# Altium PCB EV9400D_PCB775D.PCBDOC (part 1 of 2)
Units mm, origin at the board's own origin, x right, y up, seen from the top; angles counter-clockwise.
Board outline 83 x 87.15 mm, 4 copper layers (Top, L2C, L3C, Bottom), stack 1.546 mm thick; 203 components, 103 nets, 489 pads, 604 vias.
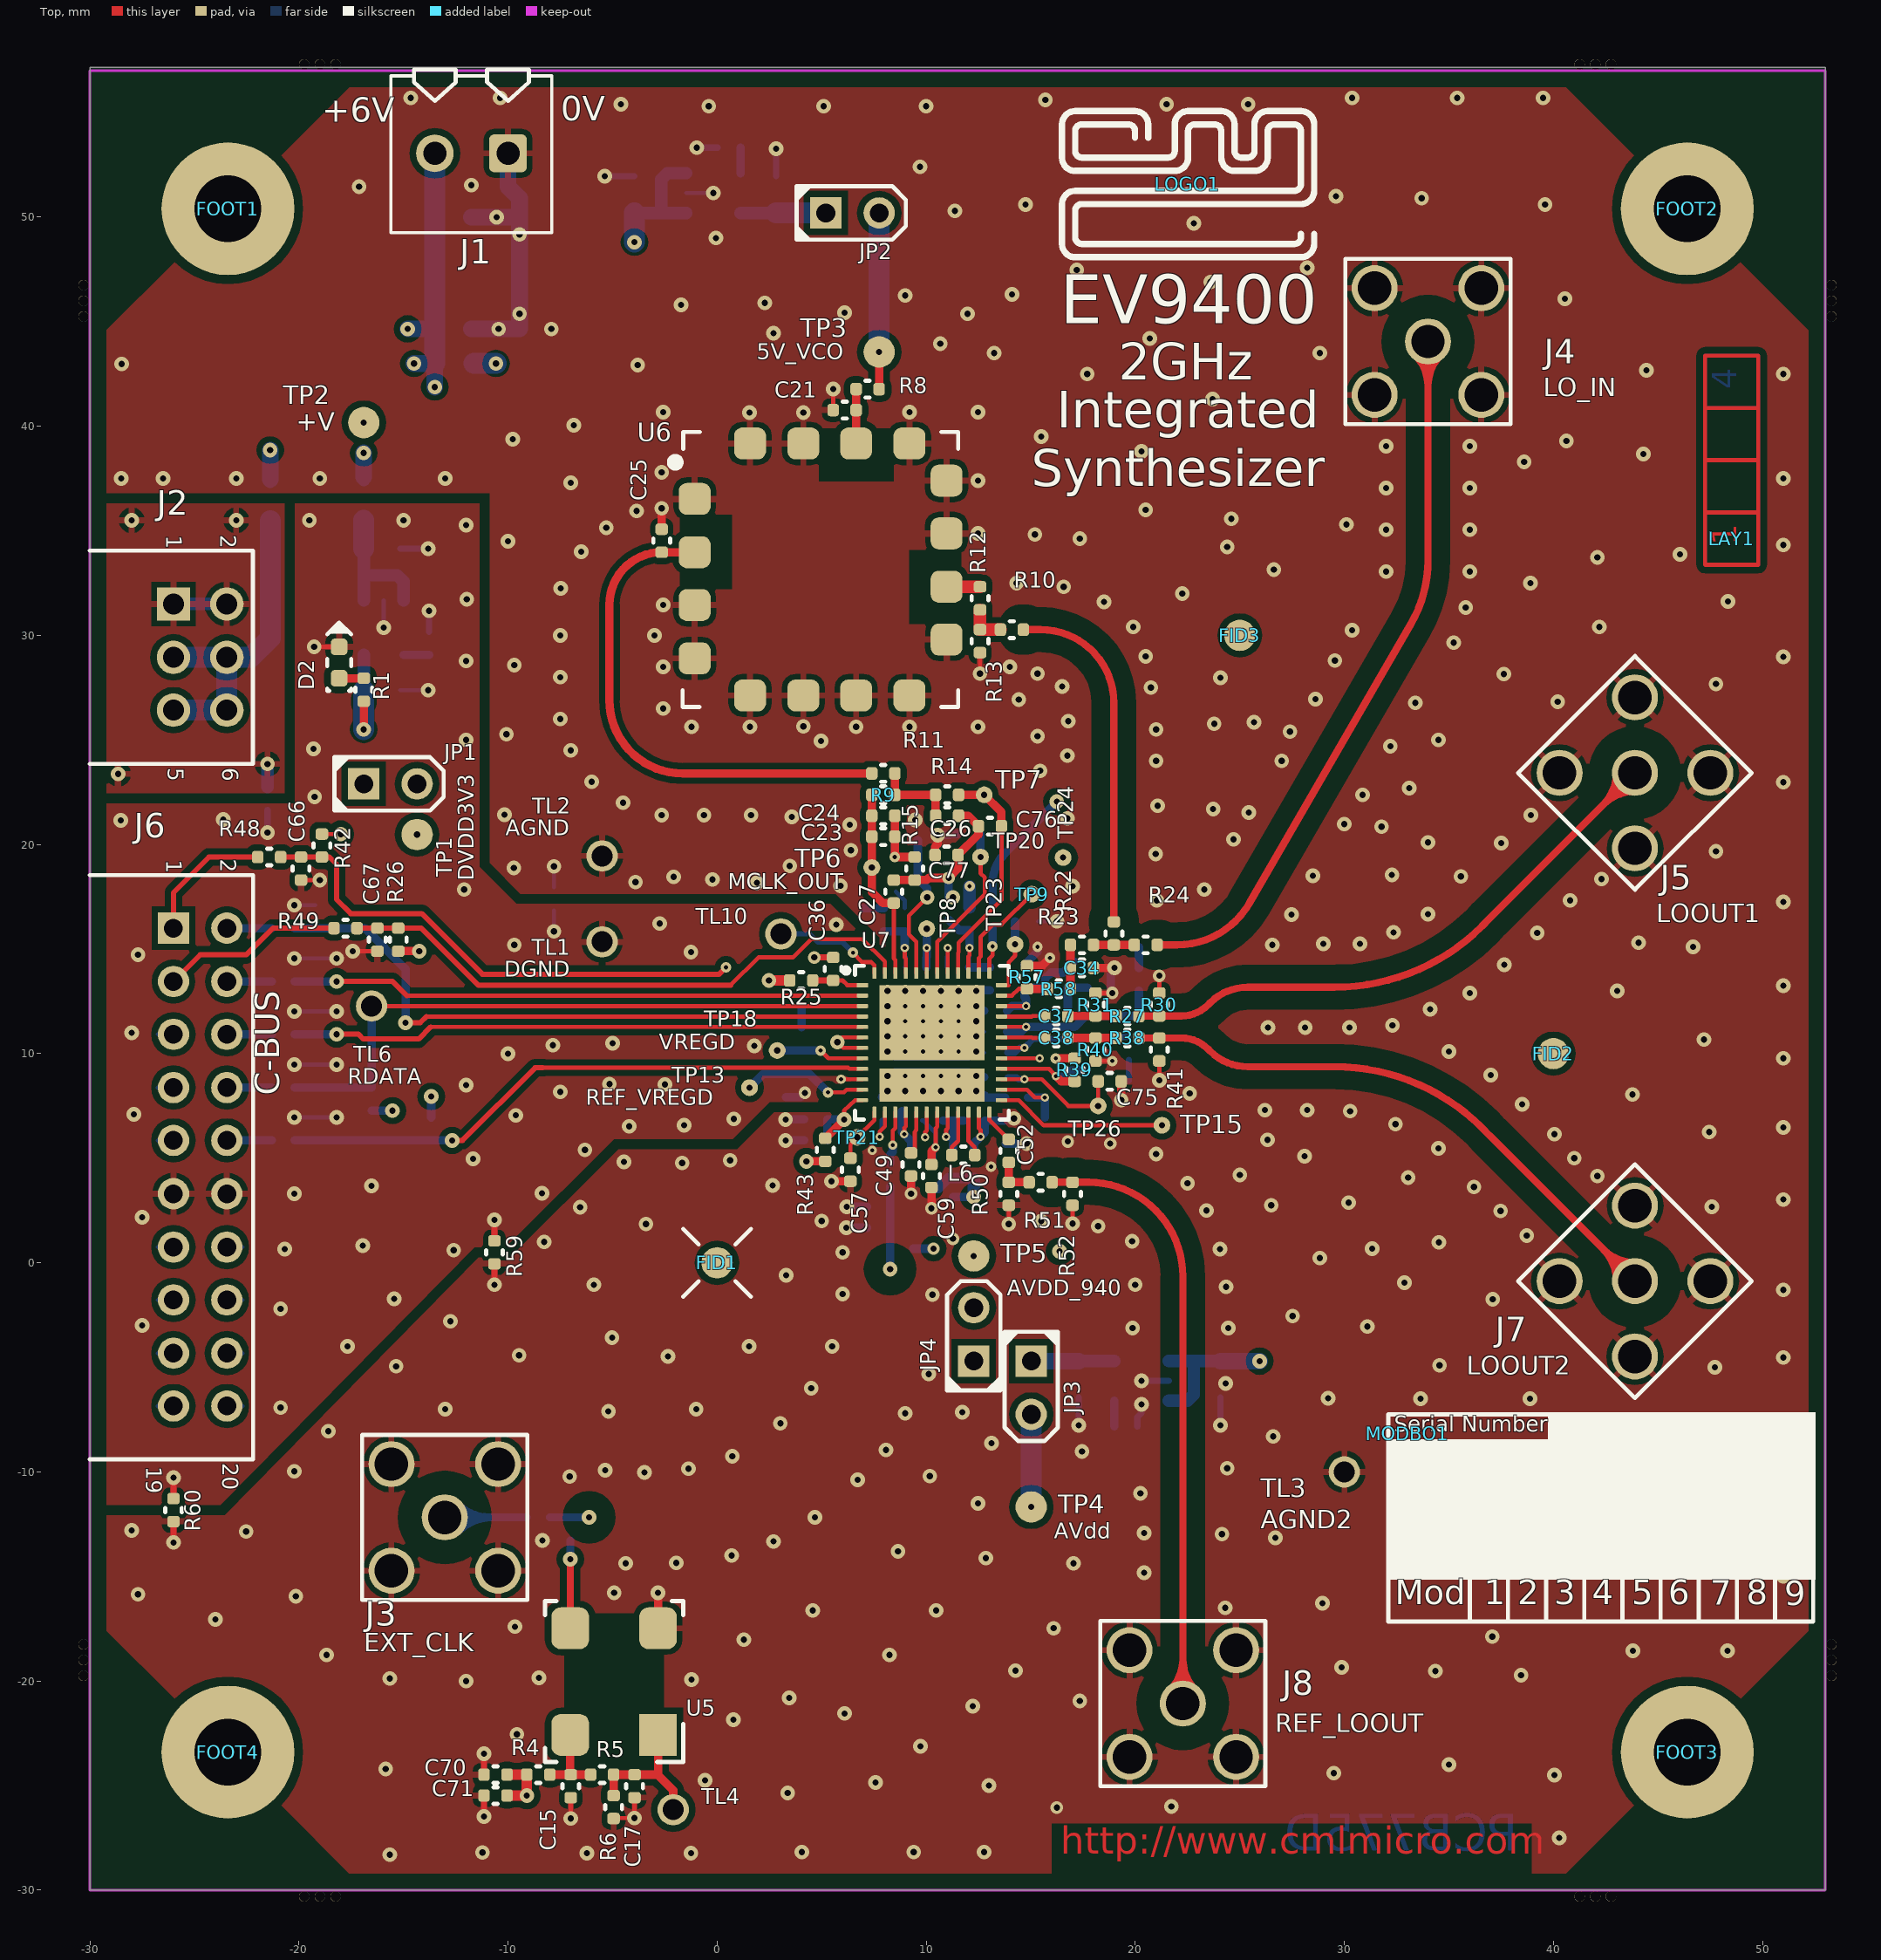
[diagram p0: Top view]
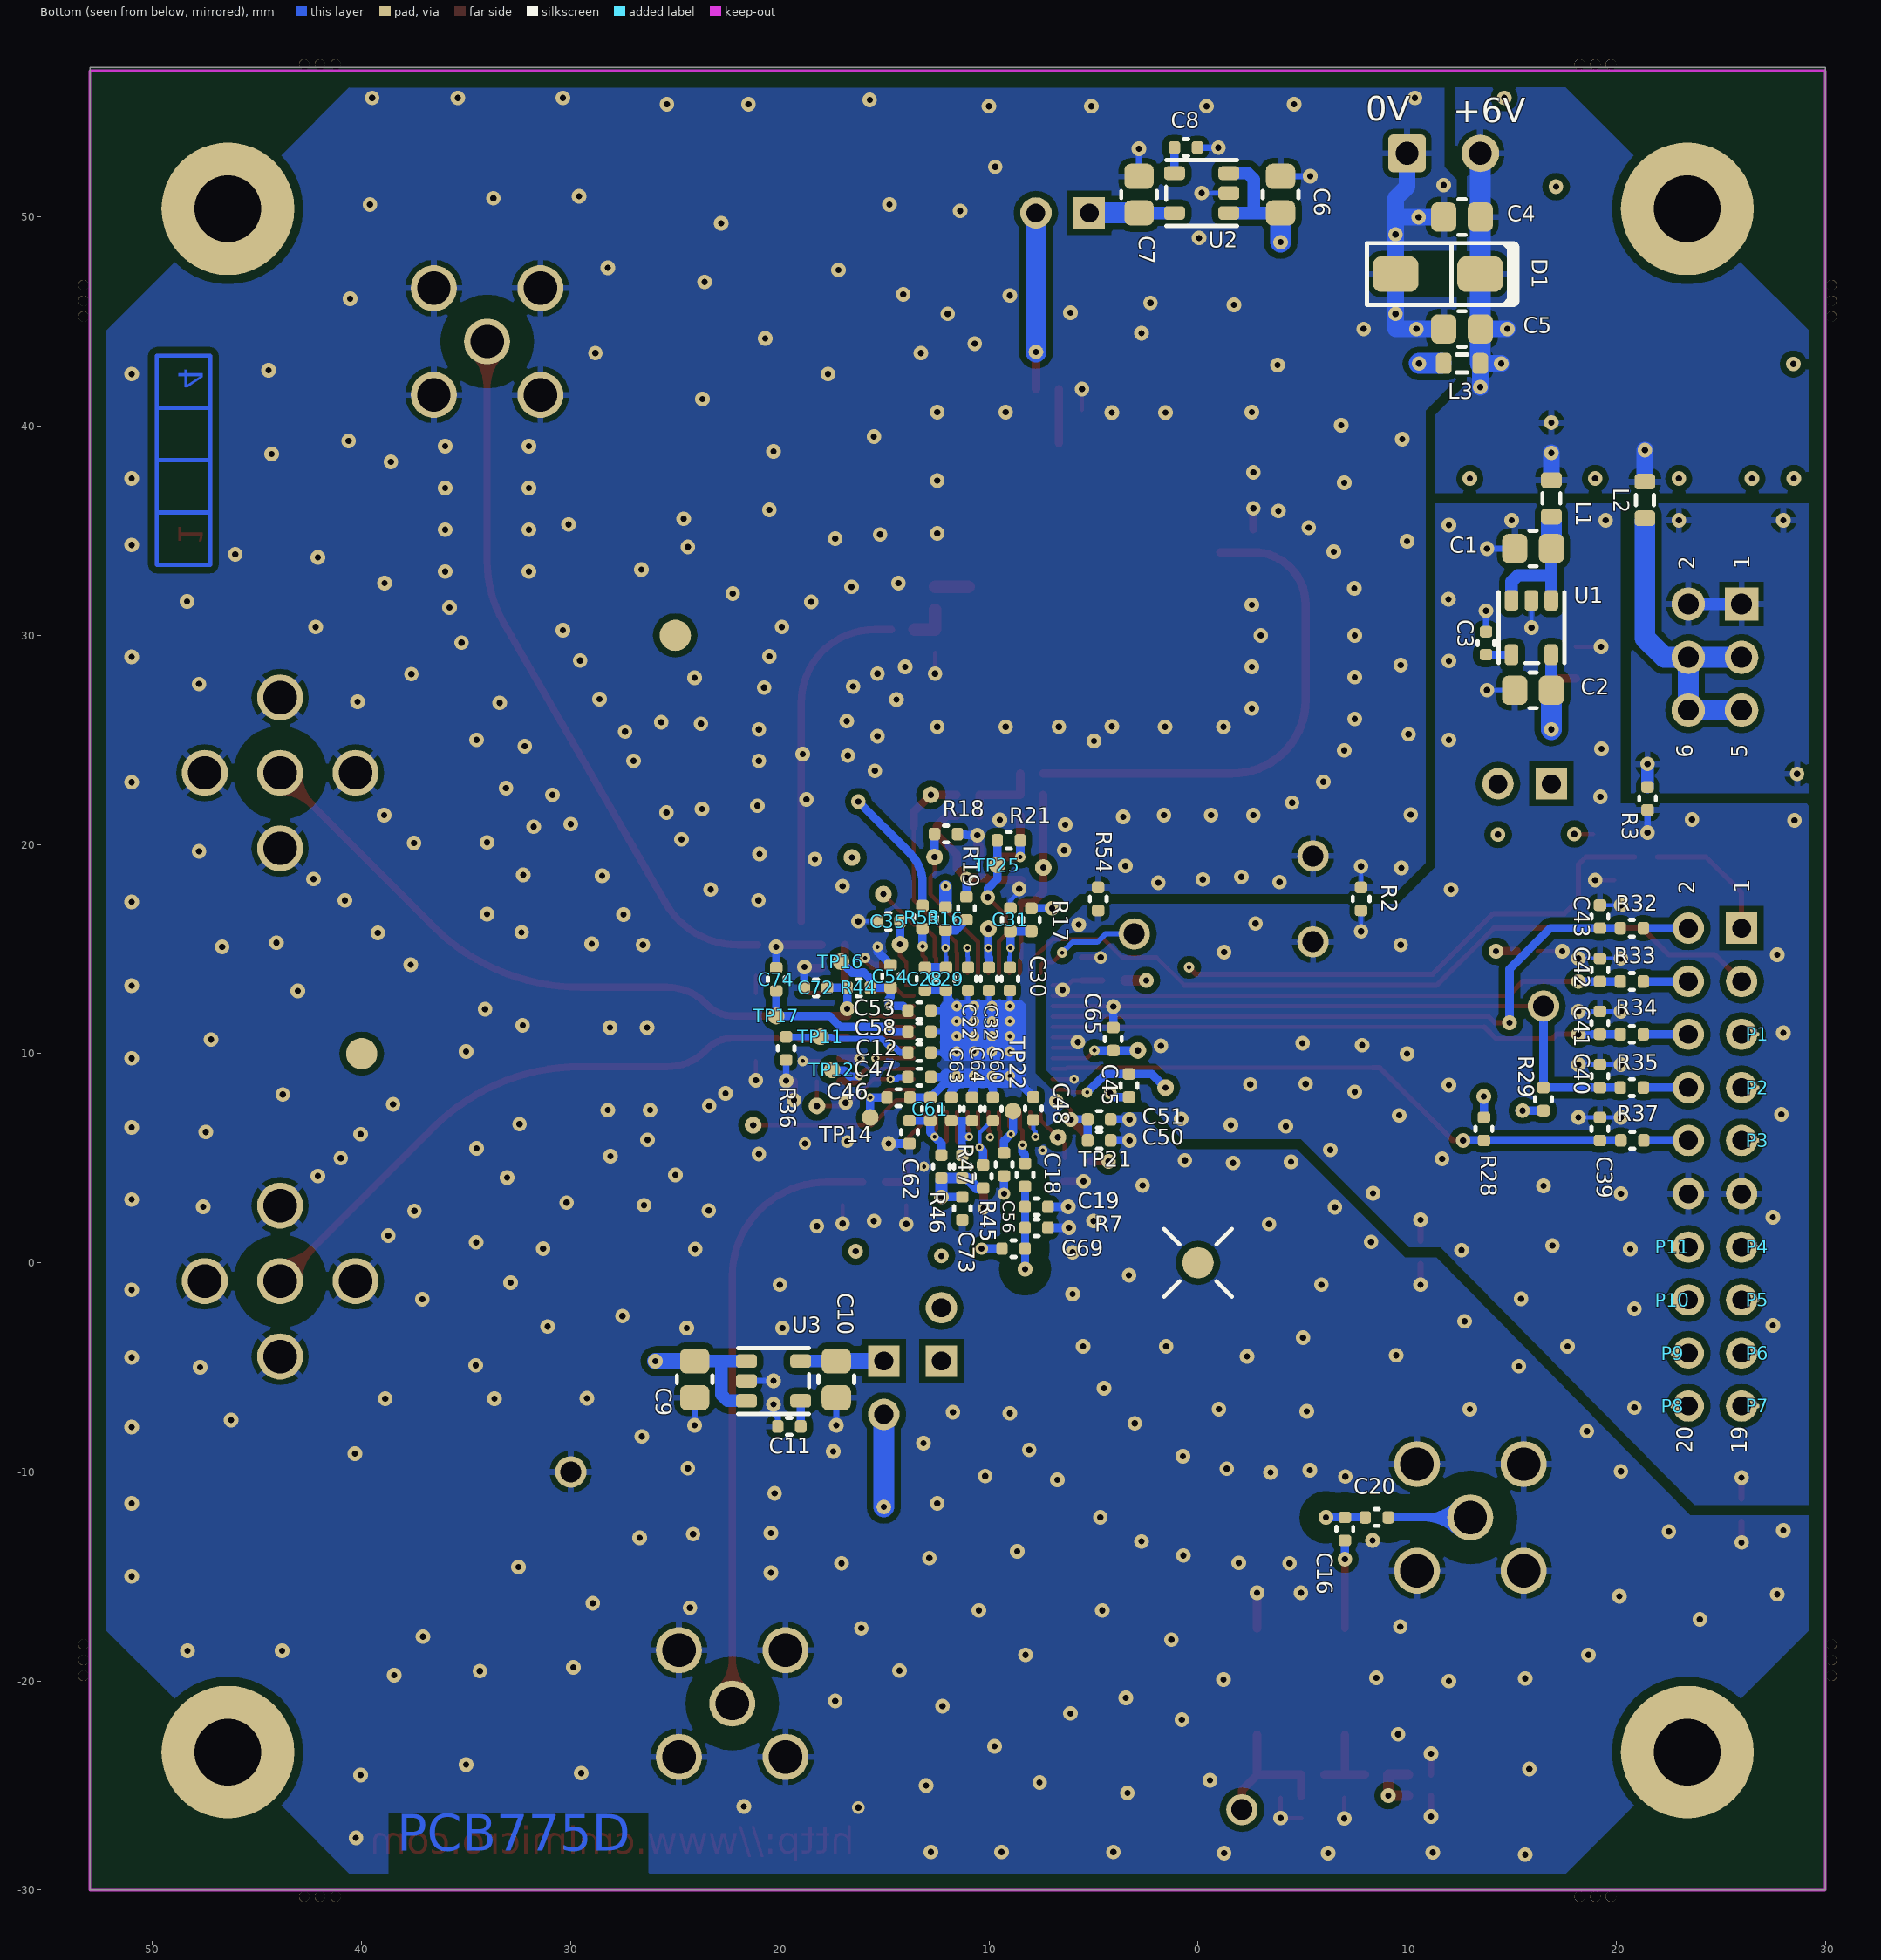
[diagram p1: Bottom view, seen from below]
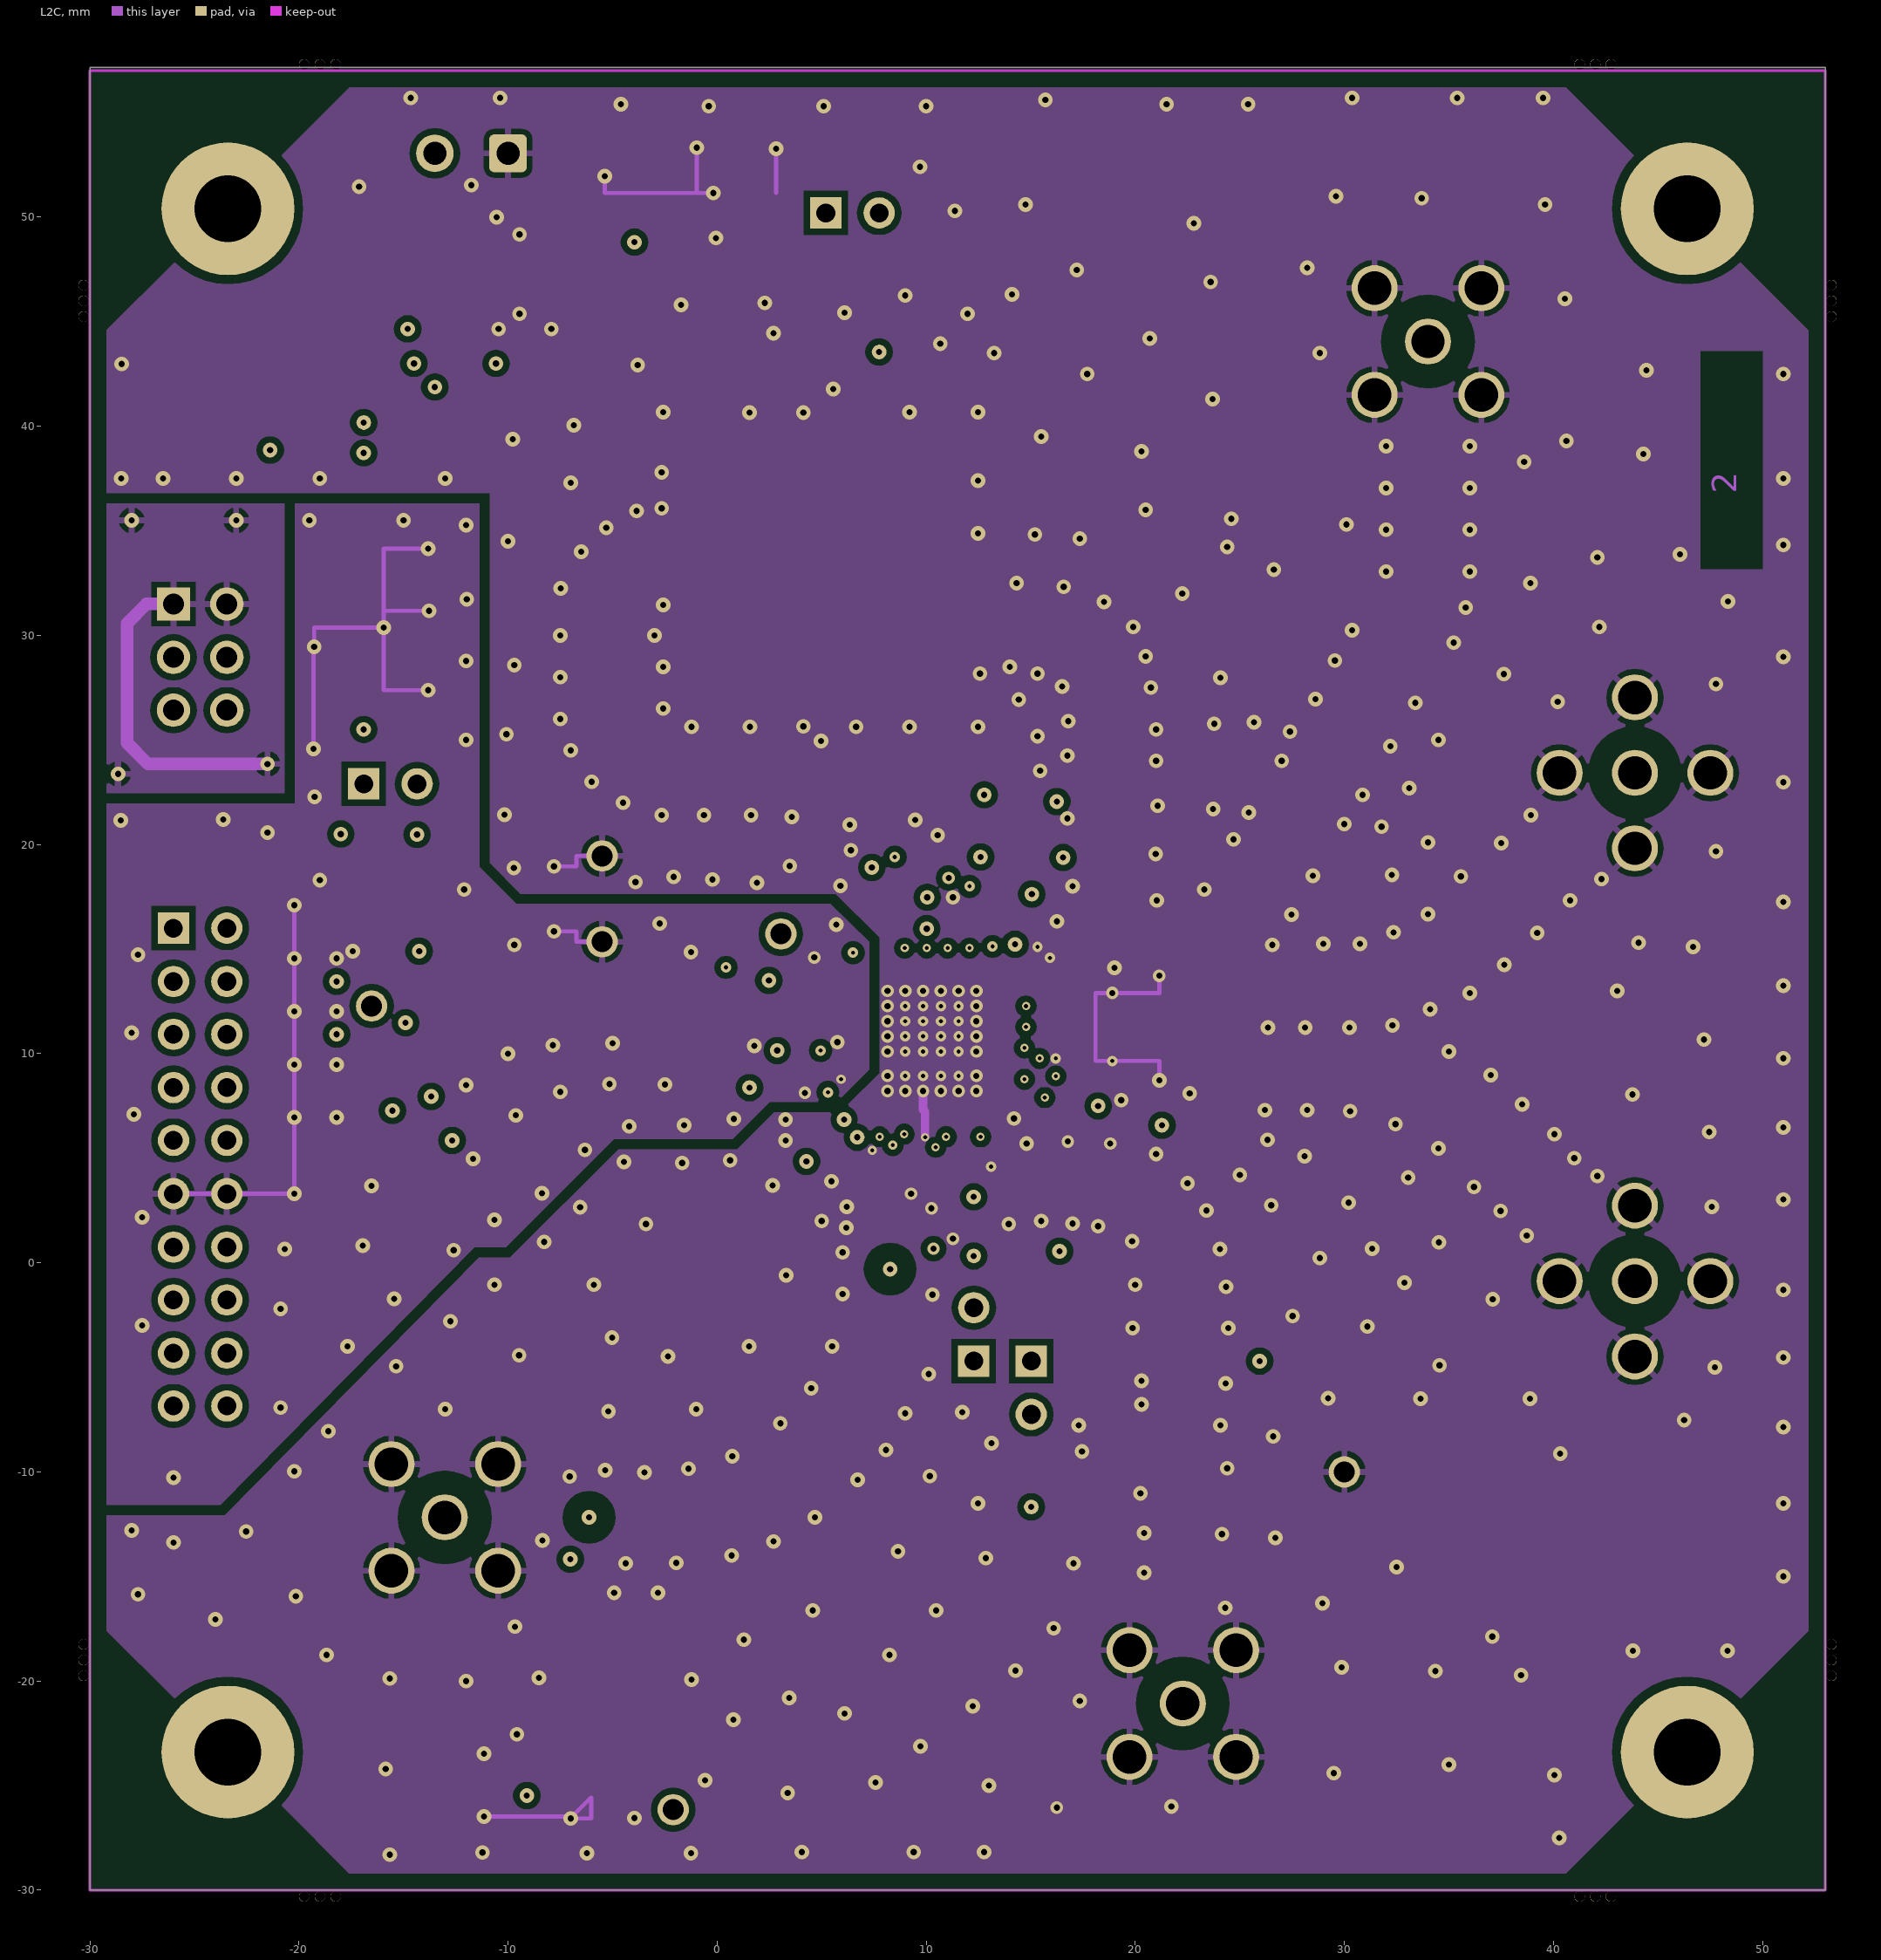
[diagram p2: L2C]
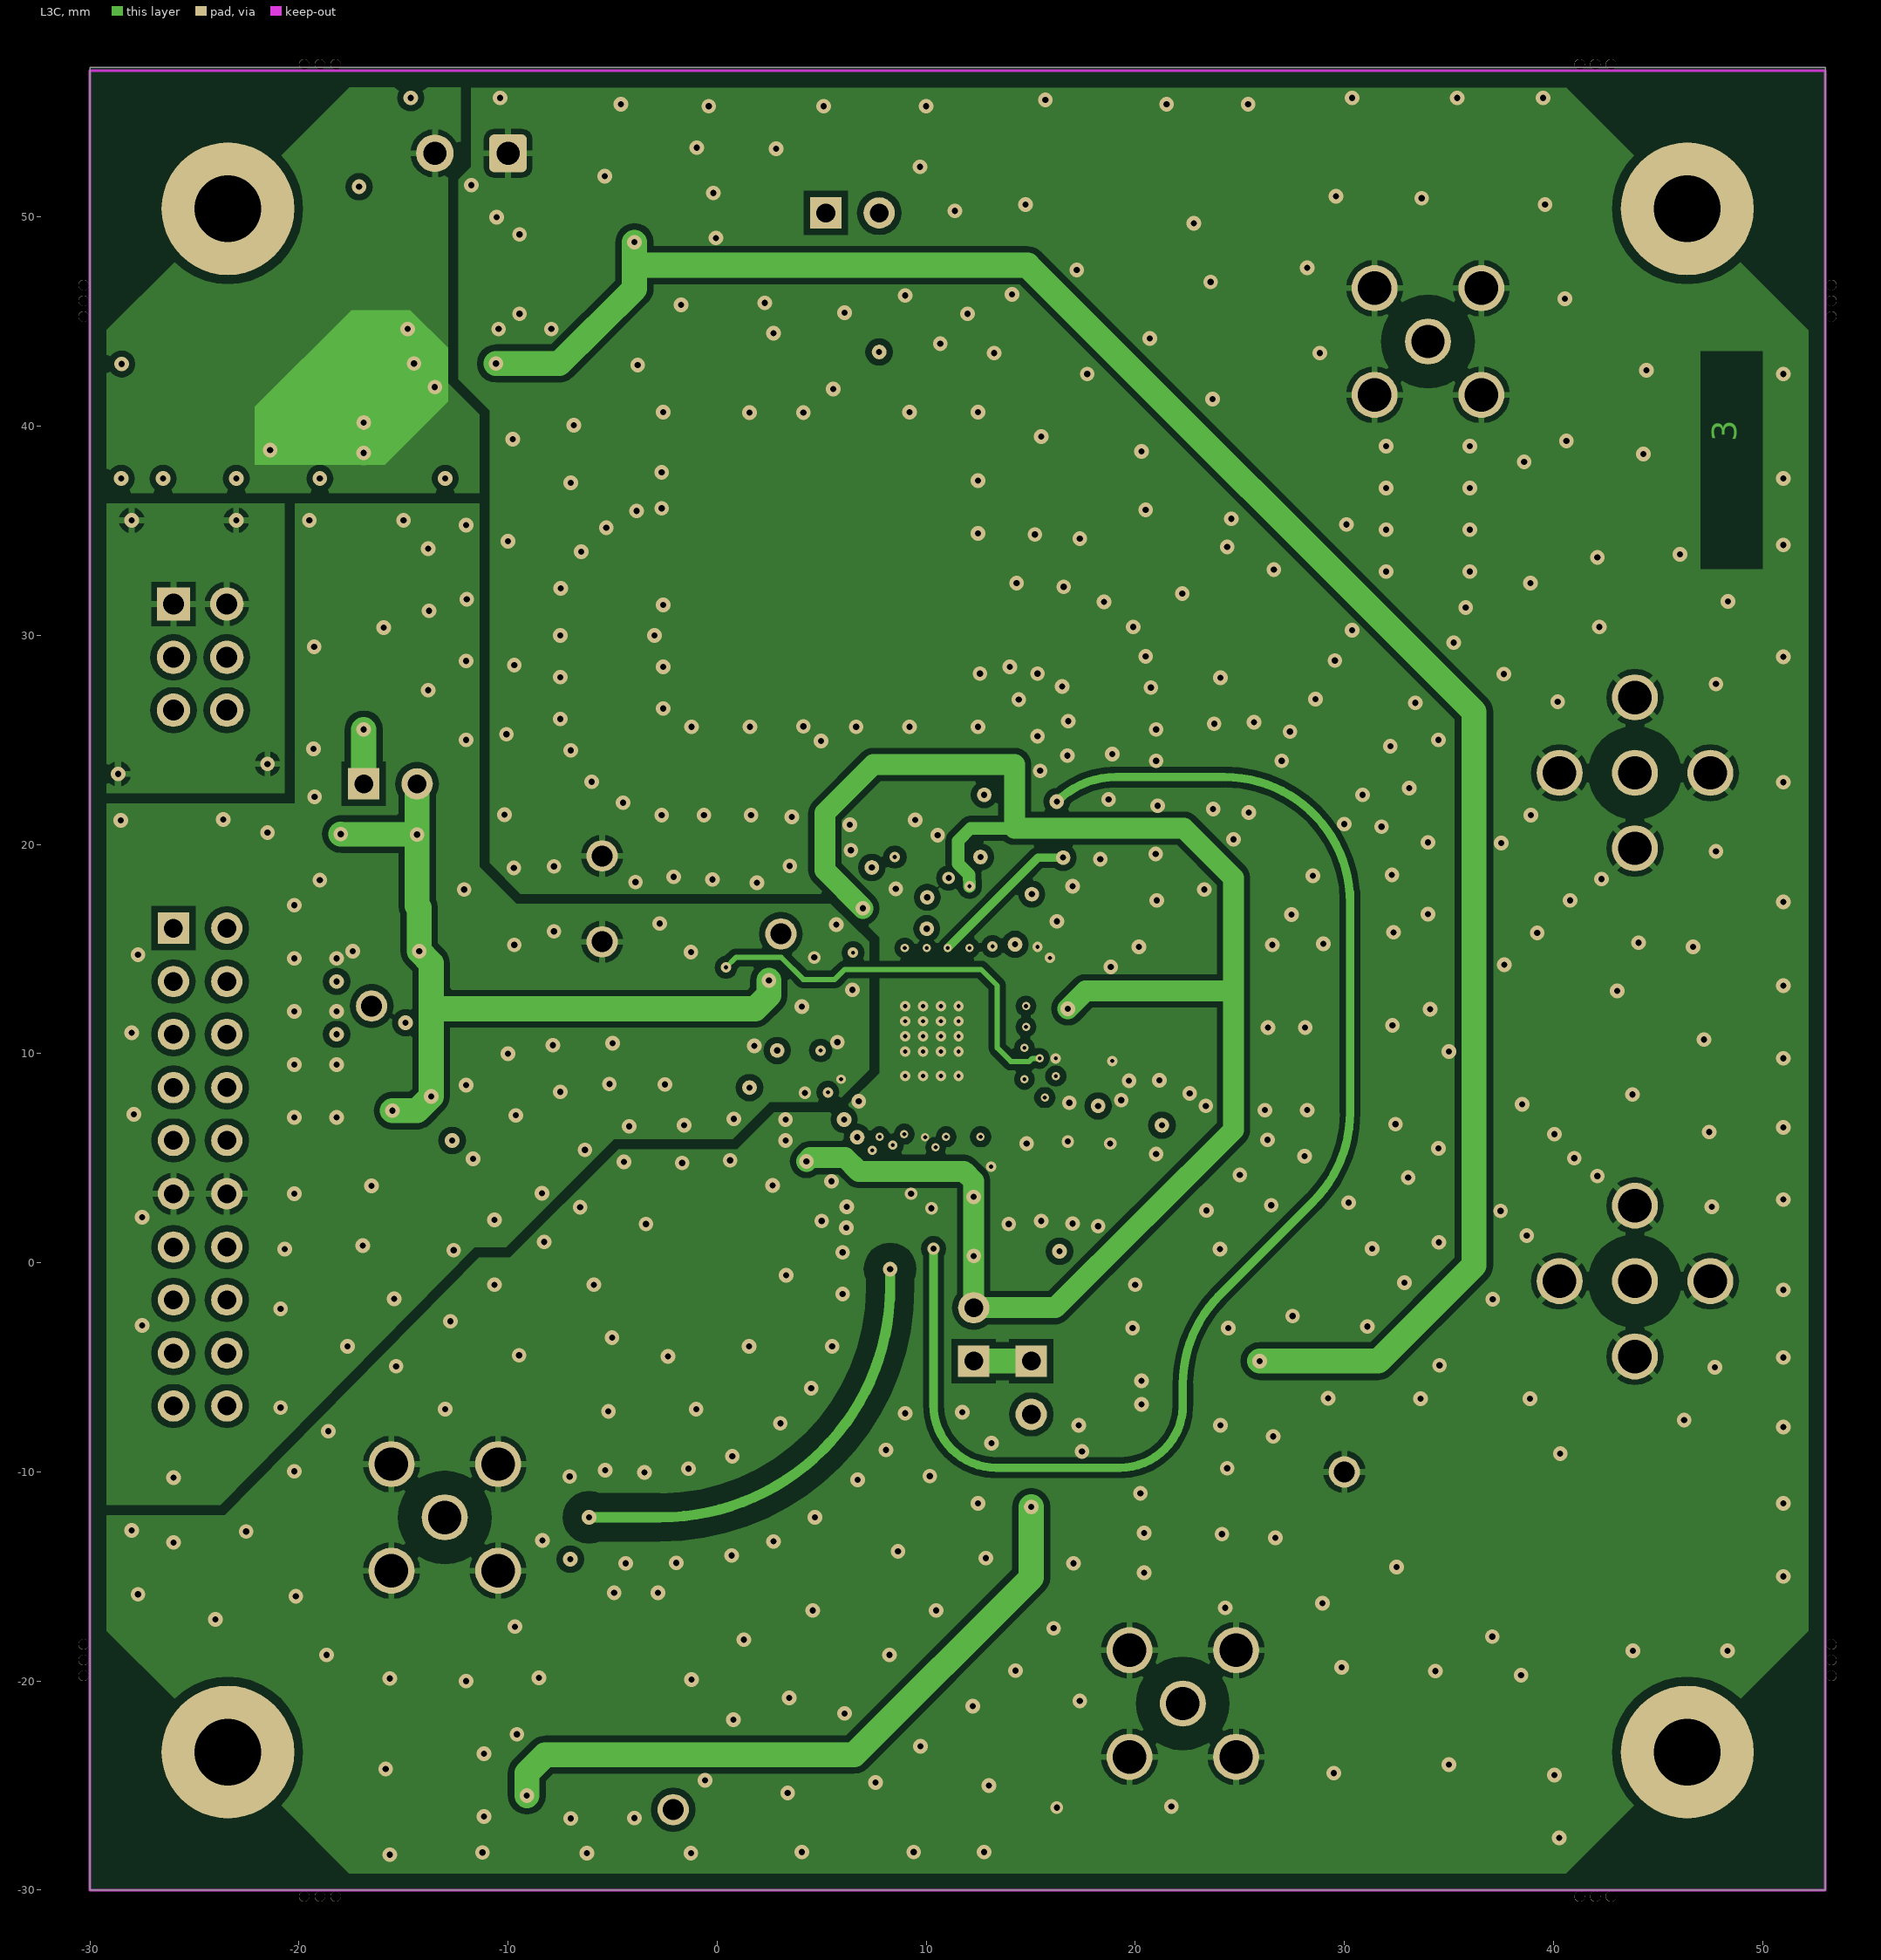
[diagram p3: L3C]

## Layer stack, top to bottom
Top: signal copper 0.043
Dielectric: prepreg 0.34, FR-4, Dk 4.8
L2C: signal copper 0.035
Dielectric: core 0.71, FR-4, Dk 4.8
L3C: signal copper 0.035
Dielectric: prepreg 0.34, FR-4, Dk 4.8
Bottom: signal copper 0.043

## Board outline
-30,-30 -30,57.15 53,57.15 53,-30

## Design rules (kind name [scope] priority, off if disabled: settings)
Clearance Clearance_50_Ohm [InNetClass('50 Ohm') vs InPolygonClass('50OHM_Clearance')] p1: gap=0.9
Clearance Clearance_Power [InNetClass('Power') vs InPolygonClass('Power')] p2: gap=0.6
Clearance "Polygon Clearance" [InPolygon] p3: gap=0.3
Clearance Clearance_Cu_PadToPad [OnCopper And IsPad vs OnCopper And IsPad] p4: gap=0.2
Clearance Clearance_Cu_PadToLine [OnCopper And IsPad vs OnCopper And IsWire] p5: gap=0.2
Clearance Clearance_Cu_LineToLine [OnCopper And IsWire vs OnCopper And IsWire] p6: gap=0.2
Clearance Clearance_Cu_ViaToPad [OnCopper And IsVia vs OnCopper And IsPad] p7: gap=0.2
Clearance Clearance_Cu_ViaToLine [OnCopper And IsVia vs OnCopper And IsWire] p8: gap=0.2
Clearance Clearance_Cu_ViaToVia [OnCopper And IsVia vs OnCopper And IsVia] p9: gap=0.2
Clearance Clearance_Design_HoleToHole [(IsVia Or IsThruPin) vs (IsVia Or IsThruPin)] p10: gap=0.2
Clearance Clearance_Region_All [(IsRegion AND NOT (InComponentClass('All Components')))] p11: gap=0.25
Clearance Clearance_1 [All] p12: gap=0.2
ComponentClearance [All] p1 off: gap=0.254 collisioncheckmode=3 verticalgap=0.254 showdistances=FALSE
DiffPairsRouting [All] p1 off: maxlimit=0.254 minlimit=0.2 mostfreqgap=0.2 maxuncoupledlength=12.7
FabricationTestPointUsage TestPointUsage [All] p1 off: valid=0 allowmultiple=FALSE
FabricationTestpoint Testpoint [All] p1 off: side=3 testpointundercomponent=TRUE minsize=1.016 maxsize=2.54 preferedsize=1.524 minholesize=0 maxholesize=1.016 preferedholesize=0.813 testpointgrid=0.025 allowsidetop=TRUE allowsidebottom=TRUE usegrid=TRUE gridtolerance=0
FanoutControl Fanout_BGA [IsBGA] p1 off: bgadir=Out bgaviamode=Centered fanoutstyle=Auto fanoutdirection=Alternating viagrid=0.025 // Fanout_BGA (Default Rule)
FanoutControl Fanout_LCC [IsLCC] p2 off: bgadir=Out bgaviamode=Centered fanoutstyle=Auto fanoutdirection=Alternating viagrid=0.025 // Fanout_LCC (Default Rule)
FanoutControl Fanout_SOIC [IsSOIC] p3 off: bgadir=Out bgaviamode=Centered fanoutstyle=Auto fanoutdirection=Alternating viagrid=0.025 // Fanout_SOIC (Default Rule)
FanoutControl Fanout_Small [(CompPinCount < 5)] p4 off: bgadir=Out bgaviamode=Centered fanoutstyle=Auto fanoutdirection=OutThenIn viagrid=0.025 // Fanout_Small (Default Rule)
FanoutControl Fanout_Default [All] p5 off: bgadir=Out bgaviamode=Centered fanoutstyle=Auto fanoutdirection=Alternating viagrid=0.025 // Fanout_Default (Default Rule)
Height [All] p1 off: minheight=0 maxheight=25.4 prefheight=12.7
HoleSize [All] p1: absolutevalues=TRUE maxlimit=4 minlimit=0.025 maxpercent=80.000 minpercent=20.000
HoleToHoleClearance [All] p1: gap=0.2 allowstackedmicrovias=TRUE
LayerPairs [All] p1 off: enforce=TRUE
MinimumSolderMaskSliver [All] p1: minsoldermaskwidth=0.1
PlaneClearance [All] p1: clearance=0.254
PolygonConnect PolygonConnect_AGND_Vias [IsVia vs InNet('AGND')] p1: connectstyle=Direct reliefconductorwidth=0.254 reliefentries=4 polygonreliefangle="90 Angle" airgapwidth=0.254
PolygonConnect PolygonConnect_AGND2_Vias [IsVia vs InNet('AGND2')] p2: connectstyle=Direct reliefconductorwidth=0.254 reliefentries=4 polygonreliefangle="90 Angle" airgapwidth=0.254
PolygonConnect PolygonConnect_DGND_Vias [IsVia vs InNet('DGND')] p3: connectstyle=Direct reliefconductorwidth=0.254 reliefentries=4 polygonreliefangle="90 Angle" airgapwidth=0.254
PolygonConnect PolygonConnect_ScrGND_Vias [IsVia vs InNet('SCRGND')] p4: connectstyle=Direct reliefconductorwidth=0.254 reliefentries=4 polygonreliefangle="90 Angle" airgapwidth=0.254
PolygonConnect PolygonConnect_+V_Vias [IsVia vs InNet('+V')] p5: connectstyle=Direct reliefconductorwidth=0.254 reliefentries=4 polygonreliefangle="90 Angle" airgapwidth=0.254
PolygonConnect [All] p6: connectstyle=Relief reliefconductorwidth=0.3 reliefentries=4 polygonreliefangle="90 Angle" airgapwidth=0.254
RoutingCorners [All] p1 off: cornerstyle=45-Degree minsetback=2.54 maxsetback=2.54
RoutingLayers [All] p1 off: top layer_v5=TRUE mid layer 1_v5=TRUE mid layer 2_v5=TRUE bottom layer_v5=TRUE
RoutingPriority [All] p1 off: routingpriority=0
RoutingTopology [All] p1 off: topology=Shortest
RoutingVias [All] p1: holewidth=0.3 width=0.7 viastyle="Through Hole" minholewidth=0.2 minwidth=0.4 maxholewidth=2 maxwidth=1.2
SilkToSilkClearance [All] p1: silktosilkclearance=0.15
SilkToSolderMaskClearance SilkscreenOverComponentPads [IsPad] p1: minsilkscreentomaskgap=0.01 clearancetoexposedcopper=TRUE
SolderMaskExpansion [All] p1: expansion=0.102
UnConnectedPin [All] p1:
Width Width_GNDA [InNet('AGND')] p1: maxlimit=2 minlimit=0.2 preferedwidth=0.5 minimp=50.000000 maximp=50.000000 favimp=50.000000 // For GNDA rings around VCOs
Width [All] p2: maxlimit=2 minlimit=0.2 preferedwidth=1 toplayer_maxwidth=1 toplayer_prefwidth=0.4 midlayer1_maxwidth=1 midlayer1_prefwidth=0.4 bottomlayer_maxwidth=1 bottomlayer_prefwidth=0.4 minimp=50.000000 maximp=50.000000 favimp=50.000000
7 further rules are at their usual default settings.

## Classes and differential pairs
polygon class 50OHM_Clearance: Bottom-GNDA L2C-AGND L3C-AGND L3C-DGND Top-GNDA
net class "50 Ohm": MCLK* NetC20_1 NetJ4_1 NetJ5_1 NetJ7_1 NetJ8_1 VCO_OUT
component class EV9400D-CMX940: C12 C21 C22 C23 C24 C25 C26 C27 C28 C29 C30 C31 C32 C34 C35 C36 C37 C38 C45 C46 C47 C48 C49 C50 C51 C52 C53 C54 C56 C57 C58 C59 C60 C61 C62 C63 C64 C65 C72 C73 C74 C75 C76 C77 J4 J5 J7 J8 J35 L6 L8 R8 R9 R10 R11 R12 R13 R14 R15 R16 R17 R18 R19 R21 R22 R23 R24 R25 R27 R30 R31 R36 R38 R39 R40 R41 R43 R44 R45 R46 R47 R50 R51 R52 R53 R57 R58 TL10 TP6 TP7 TP8 TP9 TP11 TP12 TP13 TP14 TP15 TP16 TP17 TP18 TP20 TP21 TP22 TP23 TP24 TP25 TP26 U6 U7
polygon class Power: L2C-AGND L3C-AGND L3C-DGND Top-GNDA
component class EV9400D_Power: C1 C2 C3 C4 C5 C6 C7 C8 C9 C10 C11 C15 C16 C17 C18 C19 C20 C39 C40 C41 C42 C43 C66 C67 C69 C70 C71 D1 D2 FID1 FID2 FID3 FOOT1 FOOT2 FOOT3 FOOT4 J1 J2 J3 J6 JP1 JP2 JP3 JP4 L1 L2 L3 LAY1 LOGO1 MODBO1 P1 P2 P3 P4 P5 P6 P7 P8 P9 P10 P11 R1 R2 R3 R4 R5 R6 R7 R26 R28 R29 R32 R33 R34 R35 R37 R42 R48 R49 R54 R59 R60 TL1 TL2 TL3 TL4 TL6 TP1 TP2 TP3 TP4 TP5 U1 U2 U3 U5

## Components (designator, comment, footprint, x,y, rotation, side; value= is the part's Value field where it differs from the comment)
C1 "10uF" 0805COM -15.15,34.15 r180 bottom
C2 "10uF" 0805COM -16.9,27.375 r0 bottom
C3 "DNF" 0402COM -13.775,29.075 r90 bottom
C4 "10uF" 0805COM -11.75,50 r180 bottom
C5 "DNF" 0805COM -11.75,44.65 r180 bottom
C6 "DNF" 0805COM -3.95,51.95 r270 bottom
C7 "DNF" 0805COM 2.825,50.2 r90 bottom
C8 "DNF" 0402COM 1.125,53.325 r180 bottom
C9 "10uF" 0805COM 24.075,-6.45 r90 bottom
C10 "10uF" 0805COM 17.3,-4.7 r270 bottom
C11 "DNF" 0402COM 19,-7.825 r0 bottom
C12 "33pF" 0402COM 13.875,10.05 r180 bottom
C15 "100nF" 0402COM -7,-24.475 r270 top
C16 "10nF" 0402COM -7.025,-13.275 r90 bottom
C17 "100nF" 0402COM -3.95,-25.575 r90 top
C18 "10nF" 0402COM 8.275,3.65 r90 bottom
C19 "DNF" 0402COM 8.275,2.675 r180 bottom
C20 "DNF" 0402COM -9.1,-12.175 r0 bottom
C21 "DNF" 0402COM 6.65,40.775 r180 top
C22 "470nF" 0402COM 11,14.125 r270 bottom
C23 "10nF" 0402COM 7.4,20.375 r0 top
C24 "DNF" 0402COM 7.4,21.375 r0 top
C25 "DNF" 0402COM -2.65,33.975 r90 top
C26 "33pF" 0402COM 10.45,21.375 r0 top
C27 "560pF" 0402COM 8.45,17.2 r90 top
C28 "10uF" 0402COM 13.05,14.125 r270 bottom
C29 "1000pF" 0402COM 12.05,14.125 r270 bottom
C30 "10nF" 0402COM 9,14.125 r270 bottom
C31 "100pF" 0402COM 8.975,15.85 r90 bottom
C32 "100nF" 0402COM 10,13.025 r90 bottom
C34 "DNF" 0402COM 16.9,14.1 r0 top
C35 "470nF" 0402COM 14.25,16.325 r0 bottom
C36 "10nF" 0402COM 5.55,13.5 r90 top
C37 "100pF" 0402COM 15.675,11.8 r0 top
C38 "100pF" 0402COM 15.675,10.75 r0 top
C39 "33pF" 0402COM -19.225,5.85 r90 bottom
C40 "DNF" 0402COM -19.225,8.375 r90 bottom
C41 "33pF" 0402COM -19.225,10.925 r90 bottom
C42 "33pF" 0402COM -19.225,13.45 r90 bottom
C43 "33pF" 0402COM -19.225,16 r90 bottom
C45 "100nF" 0402COM 3.3,9.025 r270 bottom
C46 "47nF" 0402COM 14.875,7.9 r180 bottom
C47 "27nF" 0402COM 13.875,8.875 r180 bottom
C48 "4.7nF" 0402COM 7.875,6.825 r90 bottom
C49 "4.7nF" 0402COM 9.275,5.25 r270 top
C50 "10nF" 0402COM 5.275,5.85 r180 bottom
C51 "100pF" 0402COM 5.275,6.85 r180 bottom
C52 "100pF" 0402COM 13.95,5.9 r270 top
C53 "100pF" 0402COM 13.875,12.05 r180 bottom
C54 "10nF" 0402COM 14.7,13.15 r90 bottom
C56 "470nF" 0402COM 9.275,5.25 r270 bottom
C57 "470nF" 0402COM 6.375,5 r270 top
C58 "100nF" 0402COM 13.875,11.05 r180 bottom
C59 "10nF" 0402COM 10.25,4.7 r270 top
C60 "100pF" 0402COM 9.8,6.8 r90 bottom
C61 "100pF" 0402COM 12.8,6.8 r90 bottom
C62 "10nF" 0402COM 13.8,6.8 r270 bottom
C63 "10nF" 0402COM 11.8,6.8 r90 bottom
C64 "100pF" 0402COM 10.8,6.8 r90 bottom
C65 "100nF" 0402COM 4.05,11.25 r270 bottom
C66 "100pF" 0402COM -19.9,19.4 r270 top
C67 "100pF" 0402COM -16.25,16 r270 top
C69 "DNF" 0402COM 8.275,0.675 r0 bottom
C70 "33pF" 0402COM -10.05,-24.475 r180 top
C71 "1000pF" 0402COM -10.05,-25.475 r180 top
C72 "1000pF" 0402COM 17.725,13.15 r0 bottom
C73 "100pF" 0402COM 11.275,3.15 r270 bottom
C74 "100pF" 0402COM 20.175,13 r90 bottom
C75 "100pF" 0402COM 18.225,8.675 r0 top
C76 "DNF" 0402COM 12.5,20.875 r0 top
C77 "DNF" 0402COM 11.525,19.5 r180 top
D1 "SMAJ5.0A+" "DO-214AC SMA" -13.5,47.275 r0 bottom
D2 "Green" LED0603 -18.075,27.95 r90 top
FID1 "Fiducial" "1.5MM Fiducial" 0,0 r0 top
FID2 "Fiducial" "1.5MM Fiducial" 40,10 r0 top
FID3 "Fiducial" "1.5MM Fiducial" 25,30 r0 top
FOOT1 "Foot" FOOT -23.4,50.4 r0 top
FOOT2 "Foot" FOOT 46.4,50.4 r0 top
FOOT3 "Foot" FOOT 46.4,-23.4 r0 top
FOOT4 "Foot" FOOT -23.4,-23.4 r0 top
J1 "MKDS_2w_3.5mm" MKDS_2 -10,53.05 r180 top
J2 "HDR_2*3RM" IDC6RM -26,31.5 r270 top locked
J3 "SMA" SMA -13.025,-12.175 r270 top
J4 "SMA" SMA 34,44.05 r0 top
J5 "SMA" SMA 43.9,23.425 r45 top
J6 "C-BUS HDR 10+10 RM" IDC20RM -26,16 r270 top locked
J7 "SMA" SMA 43.9,-0.875 r45 top
J8 "SMA" SMA 22.275,-21.075 r0 top
JP1 "Jumper2" JMP2 -16.9,22.9 r0 top
JP2 "DNF" JMP2 5.2,50.2 r0 top
JP3 "Jumper2" JMP2 15.025,-4.7 r270 top
JP4 "Jumper2" JMP2 12.275,-4.7 r90 top
L1 "600R" 0603COM -16.9,37.425 r270 bottom
L2 "DNF" 0603COM -21.375,35.6 r90 bottom
L3 "600R" 0603COM -13.5,43 r0 bottom
L6 "4.7nH" 0402COM 12.325,5.15 r180 top
LAY1 "4_LAYER_BOX" 4_LAYER_BOX 48.525,34.625 r90 top
LOGO1 "CML_LOGO" CML_LOGO 22.5,51.6 r0 top
MODBO1 "8 Mod Box" SERIAL_AND_MOD 33,-8.15 r0 top locked
P1 "PCB Pad" TINYPAD -26.75,10.925 r90 bottom
P2 "PCB Pad" TINYPAD -26.75,8.375 r180 bottom
P3 "PCB Pad" TINYPAD -26.75,5.85 r270 bottom
P4 "PCB Pad" TINYPAD -26.75,0.75 r270 bottom
P5 "PCB Pad" TINYPAD -26.75,-1.775 r270 bottom
P6 "PCB Pad" TINYPAD -26.75,-4.325 r270 bottom
P7 "PCB Pad" TINYPAD -26.75,-6.85 r270 bottom
P8 "PCB Pad" TINYPAD -22.7,-6.85 r270 bottom
P9 "PCB Pad" TINYPAD -22.7,-4.325 r270 bottom
P10 "PCB Pad" TINYPAD -22.7,-1.775 r180 bottom
P11 "PCB Pad" TINYPAD -22.7,0.75 r180 bottom
R1 "470R" 0402COM -16.9,26.85 r90 top
R2 "0R" 0402COM -7.8,17.95 r270 bottom
R3 "DNF" 0402COM -21.5,21.65 r90 bottom
R4 "100R" 0402COM -8,-24.475 r180 top
R5 "10k" 0402COM -6.05,-24.475 r0 top
R6 "10k" 0402COM -4.95,-25.475 r270 top
R7 "DNF" 0402COM 7.175,1.675 r0 bottom
R8 "DNF" 0402COM 7.75,41.775 r180 top
R9 "2.2k" 0402COM 7.4,22.375 r0 top
R10 "DNF" 0402COM 14.65,30.275 r180 top
R11 "DNF" 0402COM 7.4,23.4 r0 top
R12 "DNF" 0402COM 12.575,31.225 r90 top
R13 "DNF" 0402COM 12.575,30.275 r270 top
R14 "0R" 0402COM 11.55,22.375 r180 top
R15 "560R" 0402COM 9.45,19.4 r270 top
R16 "3.3R" 0402COM 12.075,15.9 r90 bottom
R17 "3.3R" 0402COM 7.975,16.95 r270 bottom
R18 "DNF" 0402COM 12.6,20.5 r180 bottom
R19 "10R" 0402COM 11.075,17.5 r270 bottom
R21 "DNF" 0402COM 9.6,20.2 r180 bottom
R22 "DNF" 0402COM 18.975,15.2 r90 top
R23 "0R" 0402COM 16.9,15.2 r0 top
R24 "0R" 0402COM 19.95,15.2 r0 top
R25 "10R" 0402COM 4.575,13.5 r180 top
R26 "100k" 0402COM -15.25,16 r270 top
R27 "0R" 0402COM 19.075,11.8 r0 top
R28 "100k" 0402COM -13.675,5.85 r90 bottom
R29 "100k" 0402COM -16.525,8.375 r270 bottom
R30 "DNF" 0402COM 21.15,12.9 r270 top
R31 "DNF" 0402COM 18.1,12.9 r270 top
R32 "100R" 0402COM -20.2,16 r180 bottom
R33 "100R" 0402COM -20.2,13.45 r180 bottom
R34 "100R" 0402COM -20.2,10.925 r180 bottom
R35 "100R" 0402COM -20.2,8.375 r180 bottom
R36 "47k5" 0402COM 19.7,10.8 r270 bottom
R37 "100R" 0402COM -20.225,5.85 r180 bottom
R38 "0R" 0402COM 19.075,10.75 r0 top
R39 "47k5" 0402COM 17.1,8.675 r90 top
R40 "DNF" 0402COM 18.1,9.65 r90 top
R41 "DNF" 0402COM 21.15,9.65 r90 top
R42 "100k" 0402COM -18.9,19.4 r90 top
R43 "10R" 0402COM 5.175,4.85 r90 top
R44 "3.3R" 0402COM 16.775,13.15 r180 bottom
R45 "10R" 0402COM 10.275,3.575 r90 bottom
R46 "10R" 0402COM 12.275,5.15 r270 bottom
R47 "10R" 0402COM 11.275,4.05 r90 bottom
R48 "100R" 0402COM -21.975,19.4 r0 top
R49 "100R" 0402COM -18.325,16 r0 top
R50 "DNF" 0402COM 13.95,2.75 r90 top
R51 "0R" 0402COM 14.925,3.85 r0 top
R52 "DNF" 0402COM 17,2.75 r90 top
R53 "DNF" 0402COM 13.175,15.975 r90 bottom
R54 "0R" 0402COM 4.775,17.95 r270 bottom
R57 "51R" 0402COM 14.825,13.1 r90 top
R58 "0R" 0402COM 15.8,13.1 r0 top
R59 "0R" 0402COM -10.65,-0.05 r90 top
R60 "0R" 0402COM -26,-12.375 r90 top
TL1 "1.5mm testloop (Y)" TESTLOOP_1.0MM -5.5,15.35 r90 top locked
TL2 "1.5mm testloop (Y)" TESTLOOP_1.0MM -5.5,19.45 r180 top
TL3 "1.5mm testloop (Y)" TESTLOOP_1.0MM 30,-10 r180 top
TL4 "1.5mm testloop (Y)" TESTLOOP_1.0MM -2.1,-26.15 r0 top
TL6 "1.5mm testloop (Y)" TESTLOOP_1.0MM -16.525,12.275 r270 top
TL10 "DNF" TESTLOOP_1.0MM 3.05,15.725 r270 top
TP1 "DVDD3V3" "1.5MM TSTPOINTV" -14.35,20.475 r0 top
TP2 "+V" "1.5MM TSTPOINTV" -16.9,40.175 r90 top
TP3 "5V_VCO" "1.5MM TSTPOINTV" 7.75,43.55 r90 top locked
TP4 "AVdd" "1.5MM TSTPOINTV" 15.025,-11.675 r270 top locked
TP5 "AVDD_940" "1.5MM TSTPOINTV" 12.275,0.325 r270 top
TP6 "MCLK_OUT" 0.8MM_ATE_TSTPT 7.4,18.9 r90 top locked
TP7 "SVCO_VTUNE" 0.8MM_ATE_TSTPT 12.775,22.375 r0 top locked
TP8 "VREG_DIV" 0.8MM_ATE_TSTPT 10.025,15.975 r0 top locked
TP9 "TEST" 0.8MM_ATE_TSTPT 15.05,17.625 r90 top locked
TP11 "REXT" "0.8MM ATETSTPT-SL" 18.05,10.8 r90 bottom
TP12 "REF_REXT" "0.8MM ATETSTPT-SL" 17.5,9.225 r90 bottom
TP13 "REF_VREGD" 0.8MM_ATE_TSTPT 1.55,8.375 r0 top locked
TP14 "RVCO_DEC2" "0.8MM ATETSTPT-SL" 15.675,6.95 r90 bottom locked
TP15 "MCLK_OUT" 0.8MM_ATE_TSTPT 21.275,6.575 r90 top locked
TP16 "VDD_LO" "0.8MM ATETSTPT-SL" 17.075,14.4 r90 bottom
TP17 "VREG_LO" "0.8MM ATETSTPT-SL" 20.175,11.8 r90 bottom
TP18 "VREGD" 0.8MM_ATE_TSTPT 2.875,10.15 r0 top locked
TP20 "LD" 0.8MM_ATE_TSTPT 12.6,19.4 r0 top locked
TP21 "VREG_CLK" 0.8MM_ATE_TSTPT 6.7,6 r0 top locked
TP22 "REF_VREG_CLK" "0.8MM ATETSTPT-SL" 8.85,7.25 r180 bottom locked
TP23 "SVCO_DEC1" 0.8MM_ATE_TSTPT 14.25,15.225 r0 top locked
TP24 "SVCO_DEC2" 0.8MM_ATE_TSTPT 16.55,19.375 r0 top locked
TP25 "FLCK" "0.8MM ATETSTPT-SL" 9.6,19.025 r180 bottom locked
TP26 "RVCO_DEC1" 0.8MM_ATE_TSTPT 18.225,7.5 r0 top locked
U1 "LP5907MFX-3.3" SOT23-5 -16.9,31.675 r270 bottom
U2 "DNF" SOT23-5 -1.475,50.2 r0 bottom
U3 "LP5907MFX-3.3" SOT23-5 21.6,-4.7 r180 bottom
U5 "MP07489" GTXO-74 -4.925,-20.025 r90 top
U6 "DNF" PL-012 4.95,33.15 r270 top
U7 "CMX940T1" QFN50P700X700X110_HS-50N 10.275,10.525 r0 top

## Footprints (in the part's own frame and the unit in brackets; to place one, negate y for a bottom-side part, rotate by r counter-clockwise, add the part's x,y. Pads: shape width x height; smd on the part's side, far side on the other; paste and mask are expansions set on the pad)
"0.8MM ATETSTPT-SL" [mm] "0.8mm pad on top layer 1.27mm spacing circle"
  round 0.8 smd paste-25.4: 1(0,0)
0.8MM_ATE_TSTPT [mm] "0.8mm pad 0.3mm via, 1.27mm spacing circle"
  round 0.8 / inner round 0.7 / far side round 0.8 hole 0.3 paste-25.4: 1(0,0)
"1.5MM Fiducial" [mm] "1.5mm disc in copper, 3mm disk in mask"
  round 1.5 smd paste-25.4 mask+0.2: 1(0,0)
  round 1.5 smd far side paste-25.4 mask+0.2: 1(0,0)
"1.5MM TSTPOINTV" [mm] "1.5mm testpoint with 0.3mm via"
  round 1.5 / inner round 0.7 / far side round 0.7 hole 0.3 paste-25.4: 1(0,0)
4_LAYER_BOX [mm]
  Top lines w0.2: 1.25,1.275 1.25,-1.275 ; 1.25,1.275 3.75,1.275 ; 1.25,1.275 -1.25,1.275 -1.25,-1.275 1.25,-1.275 ; 3.75,1.275 3.75,-1.275 ; 3.75,1.275 6.25,1.275 ; 6.25,1.275 6.25,-1.275 ; 6.25,1.275 8.75,1.275 8.75,-1.275 6.25,-1.275 ; 1.25,-1.275 3.75,-1.275 ; 3.75,-1.275 6.25,-1.275
  Bottom lines w0.2: 1.25,1.275 1.25,-1.275 ; 1.25,1.275 3.75,1.275 ; 1.25,1.275 -1.25,1.275 -1.25,-1.275 1.25,-1.275 ; 3.75,1.275 3.75,-1.275 ; 3.75,1.275 6.25,1.275 ; 6.25,1.275 6.25,-1.275 ; 6.25,1.275 8.75,1.275 8.75,-1.275 6.25,-1.275 ; 1.25,-1.275 3.75,-1.275 ; 3.75,-1.275 6.25,-1.275
  Multi-Layer pour cut-out: -1.45,-1.475 8.95,-1.475 8.95,1.475 -1.45,1.475
0402COM [mm]
  rrect50% 0.55x0.6 smd: 1(0,0) 2(1.1,0)
  Top pour cut-out: 0.175,-0.3 0.175,0.3 0.95,0.3 0.95,-0.3
  silkscreen extent 0.45,-0.4 0.65,0.4, body extent 0.05,-0.28 1.05,0.27, height 0.38
0603COM [mm]
  rrect50% 0.75x1 smd: 1(0,0) 2(1.75,0)
  Top pour cut-out: 0.475,-0.65 0.475,0.65 1.275,0.65 1.275,-0.65
  silkscreen extent 0.63,-0.43 1.12,0.43, body extent -0.05,-0.48 1.8,0.48, height 0.45
0805COM [mm]
  rrect50% 1.2x1.4 smd: 1(0,0) 2(1.75,0)
  Top pour cut-out: 0.2,-0.8 0.2,0.8 1.55,0.8 1.55,-0.8
  silkscreen extent 0.7,-0.85 1.05,0.85, body extent -0.18,-0.7 1.92,0.7, height 0.5
CML_LOGO [mm]
  silkscreen extent -6.01,-3.52 6.06,3.47
"DO-214AC SMA" [mm]
  rrect50% 2.2x1.7 smd: 1(0,0) 2(4.05,0)
  Top pour cut-out: 0.875,1.125 3.25,1.125 3.25,-1.125 0.875,-1.125
  silkscreen extent -1.6,-1.48 5.43,1.48
FOOT [mm]
  round 6.35 hole 3.175 unplated: 0(0,0)
GTXO-74 [mm] "QFN, 4-Leads, Body 7.03x5.03mm , IPC Medium Density"
  rect 2x1.8 smd: 1(-2.55,-2.1)
  rrect50% 2x1.8 smd: 2(2.55,-2.1) 3(2.55,2.1) 4(-2.55,2.1)
  Top pour cut-out: -3.25,-1.225 -1.55,-1.225 -1.55,-2.375 1.55,-2.375 1.55,-1.225 3.25,-1.225 3.25,1.225 1.55,1.225 1.55,2.375 -1.55,2.375 -1.55,1.225 -3.25,1.225
  silkscreen extent -3.85,-3.3 3.85,3.3, body extent -3.5,-2.5 3.5,2.5, height 2.3
IDC6RM [mm]
  rect 1.6x1.6 hole 1: 1(0,0)
  round 1.6 hole 1: 2(0,2.55) 3(2.55,0) 4(2.55,2.55) 5(5.075,0) 6(5.075,2.55)
  silkscreen extent -2.55,-4 7.65,3.8
IDC20RM [mm]
  rect 1.5x1.5 hole 0.9: 1(0,0)
  round 1.5 hole 0.9: 2(0,2.55) 3(2.55,0) 4(2.55,2.55) 5(5.075,0) 6(5.075,2.55) 7(7.625,0) 8(7.625,2.55) 9(10.15,0) 10(10.15,2.55) 11(12.7,0) 12(12.7,2.55) 13(15.25,0) 14(15.25,2.55) 15(17.775,0) 16(17.775,2.55) 17(20.325,0) 18(20.325,2.55) 19(22.85,0) 20(22.85,2.55)
  silkscreen extent -2.54,-4 25.4,3.81
JMP2 [mm]
  rect 1.5x1.5 hole 0.9: 1(0,0)
  round 1.5 hole 0.9: 2(2.55,0)
  silkscreen extent -1.4,-1.28 3.83,1.28
LED0603 [mm]
  rrect50% 0.8x0.8 smd: 1(0,0) 2(1.5,0)
  Top pour cut-out: 0.3,-0.5 1.225,-0.5 1.225,0.5 0.3,0.5
  silkscreen extent -0.6,-0.58 2.65,0.58
MKDS_2 [mm] "2-way screw terminal block, 3.5mm pitch"
  rrect25% 1.8x1.8 hole 1.1 mask+0: 1(0,0)
  round 1.8 hole 1.1 mask+0: 2(3.5,0)
  silkscreen extent -2.1,-4 5.6,3.8, body extent -2,-3.6 5.5,3.7, height 8.5
PL-012 [mm] "SM VCO 0.5in square Mini-circuits case CK605"
  rrect50% 1.525x1.525 smd: 1(-3.375,-6.025) 2(-0.825,-6.025) 3(1.7,-6.025) 4(4.25,-6.025) 5(6.025,-3.375) 6(6.025,-0.825) 7(6.025,1.7) 8(6.025,4.25) 9(3.35,6.025) 10(0.825,6.025) 11(-1.725,6.025) 12(-4.25,6.025) 13(-6.025,4.25) 14(-6.025,1.7) 15(-6.025,-0.825) 16(-6.025,-3.375)
  Top pour cut-out: 2.625,6.75 2.625,4.225 -0.95,4.225 -0.95,6.75
  Top pour cut-out: -6.75,3.5 -4.225,3.5 -4.225,-0.075 -6.75,-0.075
  Top pour cut-out: -2.625,-6.75 -2.625,-4.225 0.95,-4.225 0.95,-6.75
  silkscreen extent -6.57,-7.15 6.58,6.58, body extent -6.37,-6.37 6.38,6.38, height 4.58
QFN50P700X700X110_HS-50N [mm] "QFN, 48-Leads, Body 7.00x7.00mm, Pitch 0.50mm, Split Thermal Pad, IPC MedDensity"
  rect 0.55x0.2 smd mask-0.102: 1(-3.325,2.75)
  rrect50% 0.55x0.2 smd mask-0.102: 2(-3.325,2.25) 3(-3.325,1.75) 4(-3.325,1.25) 5(-3.325,0.75) 6(-3.325,0.25) 7(-3.325,-0.25) 8(-3.325,-0.75) 9(-3.325,-1.25) 10(-3.325,-1.75) 11(-3.325,-2.25) 12(-3.325,-2.75) 25(3.325,-2.75) 26(3.325,-2.25) 27(3.325,-1.75) 28(3.325,-1.25) 29(3.325,-0.75) 30(3.325,-0.25) 31(3.325,0.25) 32(3.325,0.75) 33(3.325,1.25) 34(3.325,1.75) 35(3.325,2.25) 36(3.325,2.75)
  rrect50% 0.2x0.55 smd mask-0.102: 13(-2.75,-3.325) 14(-2.25,-3.325) 15(-1.75,-3.325) 16(-1.25,-3.325) 17(-0.75,-3.325) 18(-0.25,-3.325) 19(0.25,-3.325) 20(0.75,-3.325) 21(1.25,-3.325) 22(1.75,-3.325) 23(2.25,-3.325) 24(2.75,-3.325) 37(2.75,3.325) 38(2.25,3.325) 39(1.75,3.325) 40(1.25,3.325) 41(0.75,3.325) 42(0.25,3.325) 43(-0.25,3.325) 44(-0.75,3.325) 45(-1.25,3.325) 46(-1.75,3.325) 47(-2.25,3.325) 48(-2.75,3.325)
  rect 5.03x3.6 smd paste-2: 49(0,0.955)
  rect 5.03x1.59 smd paste-2 mask+0.125: 50(0,-2.03)
  silkscreen extent -4.22,-3.68 3.68,3.67, body extent -3.52,-3.53 3.53,3.52, height 1.1
SERIAL_AND_MOD [mm]
  silkscreen extent -1,-9 19.53,1
SMA [mm]
  round 2.2 hole 1.6: 1(0,0) 2(-2.55,2.55) 3(-2.55,-2.55) 4(2.55,-2.55) 5(2.55,2.55)
  Multi-Layer pour cut-out: 0,-2.225 0.851,-2.056 1.573,-1.573 2.056,-0.851 2.225,0 2.225,0 2.056,0.851 1.573,1.573 0.851,2.056 0,2.225 0,2.225 -0.851,2.056 -1.573,1.573 -2.056,0.851 -2.225,0 -2.225,0 -2.056,-0.851 -1.573,-1.573 -0.851,-2.056 0,-2.225
  silkscreen extent -3.95,-3.95 3.95,3.95
SOT23-5 [mm]
  rrect50% 1x0.65 smd mask+0.175: 1(0,0) 2(0,-0.95) 3(0,-1.9) 4(2.6,-1.9) 5(2.6,0)
  silkscreen extent -0.4,-2.52 3,0.63
TESTLOOP_1.0MM [mm]
  round 1.5 hole 1: 1(0,0)
TINYPAD [mm]
  rrect50% 0.2x0.2 smd paste-25.4: 1(0,0)

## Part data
C1 C2 C4 C9 C10: library part CAP0805_10000000_X7R_10V_±10%, "0805 Cer. Cap. 10uF±10% 10V X7R"
C3 C8 C11 C19 C20 C21 C24 C25 C34 C40 C69 C76 C77: library part CAP0402_DNF, "Pads for 0402 Ceramic Capacitor"
C5 C6 C7: library part CAP0805_DNF, "Unused pads for 0805 Ceramic Capacitor"
C12 C26 C39 C41 C42 C43 C70: library part CAP0402_33p±5%_C0G_25V, "0402 Cer. Cap. 33pF±5% 25V C0G"
C15 C17 C32 C45 C58 C65: library part CAP0402_100000_X7R_16V_±10%, "0402 Cer. Cap. 100nF 16V X7R ±10%"
C16 C18 C23 C30 C36 C50 C54 C59 C62 C63: library part CAP0402_10000_X7R_25V_±10%, "0402 Cer. Cap. 10nF 25V X7R ±10%"
C22 C35 C56 C57: library part CAP0402_470000_X5R_10V_±10%, "0402 Cer. Cap. 470nF 10V X5R ±10%"
C27: library part "CAP0402_560p_C0G_25V_± 5%", "0402 Cer. Cap. 560pF±5% 25V C0G"
C28: library part CAP0402_10000000_X5R_6V3_±20%, "0402 Cer. Cap. 10uF 6V3 X5R ±20%"
C29 C71 C72: library part "CAP0402_1000_C0G_25V_± 5%", "0402 Cer. Cap. 1000pF±5% 25V C0G"
C31 C37 C38 C51 C52 C53 C60 C61 C64 C66 C67 C73 C74 C75: library part "CAP0402_100p_C0G_25V_± 5%", "0402 Cer. Cap. 100pF±5% 25V C0G"
C46: library part CAP0402_47000_X7R_25V_±10%, "0402 Cer. Cap. 47nF 25V X7R ±10%"
C47: library part CAP0402_27000_X7R_25V_±10%, "0402 Cer. Cap. 27nF 25V X7R ±10%"
C48 C49: library part CAP0402_4700_X7R_25V_±5%, "0402 Cer. Cap. 4.7nF 25V X7R ±5%"
D1: library part SMAJ5_0A, "5V Transient Suppression Diode, DO-214AC"
D2: library part LED0603_Green, "Green 0603 LED, KPT-1608CGCK"
FID1 FID2 FID3: "1.5mm round pad Fiducial"
FOOT1 FOOT2 FOOT3 FOOT4: library part FOOT, "12.7mm square stick-on foot"
J1: library part MKDS_2w_3_5mm, "2-WAY PCB screw terminal block - MKDS 1/ 2-3,5 HT BK"
J2: "3+3 double row 0.1in header right angle"
J3 J4 J5 J7 J8: library part SMA_STRAIGHT, "PCB Mounted SMA Socket (Upright)"
J6: library part HDR_10*2_CBUS_RM, "C-BUS R/A Male Header"
JP1 JP3 JP4: library part JUMPER2, "Pin header 2X1"
JP2: library part JUMPER2_DNF, "Holes for Pin header 2X1"
L1 L3: library part "Ferrite 0603_600R", "Ferrite, 0603, 600R @ 100MHz 1.3A"
L2: library part IND0603HP_DNF, "Pads for Coilcraft 0603 Inductor"
L6: library part IND0402DC_4n7_2%, "0402 inductor, 4.7nH, 0402DC-4N7XGR"
MODBO1: library part SERIAL_AND_MODBOX, "SERIAL_AND_MODBOX"
P1 P2 P3 P4 P5 P6 P7 P8 P9 P10 P11: library part TINY_PAD, "Very Small Pad - used to remove all of the 'unconnected pin' errors from ERC & DRC"
R1: library part R0402_470R, "Resistor 0402 470R 1% 0.063W  ( 66A = 475R )"
R2 R14 R23 R24 R27 R38 R51 R54 R58 R59 R60: library part R0402_0R, "Resistor 0402 0R 0.063W"
R3 R7 R8 R10 R11 R12 R13 R18 R21 R22 R30 R31 R40 R41 R50 R52 R53: library part R0402_DNF, "Pads for Resistor 0402"
R4 R32 R33 R34 R35 R37 R48 R49: library part R0402_100R, "Resistor 0402 100R 1% 0.063W  ( 01A )"
R5 R6: library part R0402_10000_10k, "Resistor 0402 10k 1% 0.063W  ( 01C )"
R9: library part R0402_2200_2k2, "Resistor 0402 2.2k 1% 0.063W  (34B = 2.21k )"
R15: library part R0402_560R, "Resistor 0402 560R 1% 0.063W  ( 73A = 562R )"
R16 R17 R44: library part R0402_3R3, "Resistor 0402 3.3R 1% 0.063W   ( 51Y )"
R19 R25 R43 R45 R46 R47: library part R0402_10R, "Resistor 0402 10R 1% 0.063W   ( 01X )"
R26 R28 R29 R42: library part R0402_100000_100k, "Resistor 0402 100k 1% 0.063W  ( O1D )"
R36 R39: library part R0402_47500_47k5, "Resistor 0402 47k5 1% 0.063W  ( 66C = 47.5k )"
R57: library part R0402_51R, "Resistor 0402 51R 1% 0.063W  ( 69X = 51.1R )"
TL1 TL2 TL3 TL4 TL6: library part TESTLOOP_1MM, "Yellow 1.5mm testloop (1.0 mm hole)"
TL10: library part TESTLOOP_1MM_DNF, "1mm hole  for 1.5mm testloop e.g. Rapid  17-1819"
TP1 TP2 TP3 TP4 TP5: library part "1.5MM TSTPOINTV", "1.5mm Testpoint with via"
TP6 TP7 TP8 TP9 TP13 TP15 TP18 TP20 TP21 TP23 TP24 TP26: library part "0.8MM ATE_TSTPT", "0.8mm pad 0.3mm via, 1.27mm spacing circle"
TP11 TP12 TP14 TP16 TP17 TP22 TP25: library part "0.8MM ATE_TSTPT_SL", "0.8mm pad top only, 1.27mm spacing circle"
U1 U3: "LP5907MFX-3.3,   3.3V, 250mA ULN Low-IQ LDO Regulator, SOT23-5"
U2: library part LP2985_DNF, "Pads for LP2985 regulator, SOT23-5"
U5: "38.40MHz GTXO-74V/JI SM Sine VCTCXO 2.5ppm"
U6: library part VCO_DNF, "Pads for 0.5in VCO module"
U7: "CMX940T1, High Performance Synthesizer"

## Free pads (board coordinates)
  round 0.5 hole 0.5 unplated mask-0.102: 0(-30.3,-19.75) 0(-30.3,-19) 0(-30.3,-18.25) 0(-30.3,45.25) 0(-30.3,46) 0(-30.3,46.75) 0(-19.75,-30.3) 0(-19.75,57.3) 0(-19,-30.3) 0(-19,57.3) 0(-18.25,-30.3) 0(-18.25,57.3) 0(41.25,-30.3) 0(41.25,57.3) 0(42,-30.3) 0(42,57.3) 0(42.75,-30.3) 0(42.75,57.3) 0(53.3,-19.75) 0(53.3,-19) 0(53.3,-18.25) 0(53.3,45.25) 0(53.3,46) 0(53.3,46.75)

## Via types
v1: diameter 0.7, hole 0.3, Top to Bottom, tented both sides, 484 vias
v2: diameter 0.6, hole 0.3, Top to L2C, 22 vias
v3: diameter 0.5, hole 0.2, Top to Bottom, tented bottom, 20 vias
v4: diameter 0.7, hole 0.3, Top to L2C, tented both sides, 19 vias
v5: diameter 0.7, hole 0.3, L3C to Bottom, tented both sides, 14 vias
v6: diameter 0.5, hole 0.2, Top to Bottom, tented both sides, 11 vias
v7: diameter 0.4, hole 0.2, Top to Bottom, tented both sides, 10 vias
v8: diameter 0.6, hole 0.3, Top to Bottom, tented both sides, 9 vias
v9: diameter 0.4, hole 0.2, Top to Bottom, tented bottom, 7 vias
v10: diameter 0.45, hole 0.2, Top to Bottom, tented both sides, 3 vias
v11: diameter 0.6, hole 0.3, Top to L2C, tented both sides, 3 vias
v12: diameter 0.7, hole 0.3, Top to Bottom, 1 vias
v13: diameter 0.5, hole 0.2, Top to Bottom, 1 vias

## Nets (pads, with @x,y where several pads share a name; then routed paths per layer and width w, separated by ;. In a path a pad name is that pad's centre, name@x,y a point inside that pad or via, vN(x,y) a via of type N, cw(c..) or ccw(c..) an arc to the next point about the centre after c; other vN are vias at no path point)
5V_VCO: JP2.2 R8.1 TP3.1 | length 8.4
  Top w0.4: R8.1@7.75,41.775 TP3.1@7.75,43.55
  Bottom w1: TP3.1@7.75,43.55 JP2.2@7.75,50.2
+5V_PE0003: J2.3 J2.4 J2.5 J2.6 L2.1 | length 15.8
  Bottom w0.6: L2.1@-21.375,35.475 L2.1@-21.375,35.6
  Bottom w1: J2.5@-26,26.425 J2.6@-23.45,26.425 J2.4@-23.45,28.95 ; J2.3@-26,28.95 J2.4@-23.45,28.95 ; L2.1@-21.375,35.475 -21.375,29.875 -22.3,28.95 J2.4@-23.45,28.95
+V: C4.2 C5.2 D1.1 J1.2 L1.1 L2.2 L3.1 TP2.1 | length 31.6
  L3C w1.2: v1@-21.375,38.9 -21.375,40.225 -16.95,44.65 v1(-14.8,44.65) ; v1(-16.9,38.725) TP2.1@-16.9,40.175 -16,41.075 -14.3,41.075 v1(-13.5,41.875)
  Bottom w0.6: L2.2@-21.375,37.35 L2.2@-21.375,37.475 ; L1.1@-16.9,37.425 L1.1@-16.9,37.575 ; L3.1@-13.575,43 L3.1@-13.5,43
  Bottom w0.8: L2.2@-21.375,37.475 v1(-21.375,38.86) ; L1.1@-16.9,37.575 v1(-16.9,38.725) ; v1(-14.8,44.65) C5.2@-13.5,44.65 ; v1(-14.5,43) L3.1@-13.575,43 ; v1(-13.5,41.875) L3.1@-13.5,43
  Bottom w1: L3.1@-13.5,43 C5.2@-13.5,44.65 D1.1@-13.5,47.275 C4.2@-13.5,50 J1.2@-13.5,53.05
